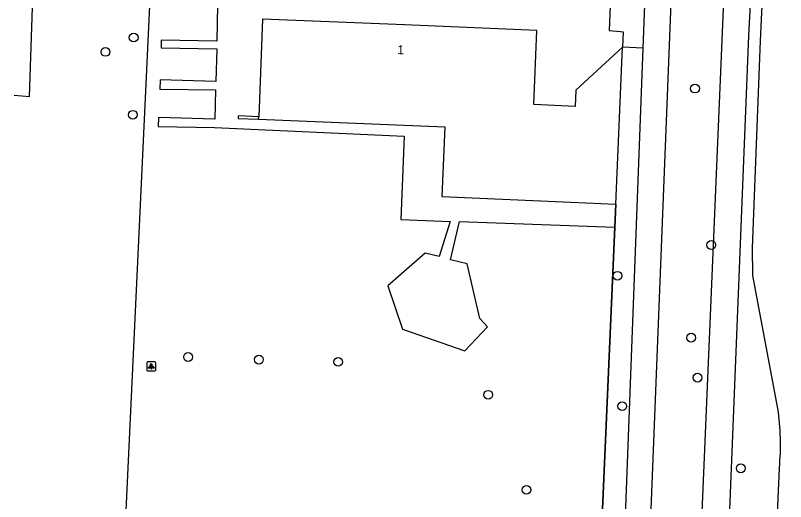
# Model space of a CAD drawing. Extents: x 159053 to 160041, y 380450 to 381422.
# Drawn here: x 159897.6 to 159983.4, y 380755.6 to 380809.7 of the extents above; entities that cross this region are included whole.
import ezdxf

# ---------------------------------------------------------------- set-up
doc = ezdxf.new("R2010")
doc.units = 0
for name, color, linetype in [('IMGEO_Boom', 7, 'Continuous'), ('IMGEO_Fietspad_gesloten', 7, 'Continuous'), ('IMGEO_Groenvoorziening', 7, 'Continuous'), ('IMGEO_Hek', 7, 'Continuous'), ('IMGEO_Lichtpunt', 7, 'Continuous'), ('IMGEO_Loofbos', 7, 'Continuous'), ('IMGEO_Muur', 7, 'Continuous'), ('IMGEO_Pand', 7, 'Continuous'), ('IMGEO_Pand_nummerreeks', 7, 'Continuous'), ('IMGEO_Waterloop', 7, 'Continuous')]:
    doc.layers.add(name, color=color, linetype=linetype)

msp = doc.modelspace()

# ---------------------------------------------------------------- linework, layer by layer
at = {"layer": 'IMGEO_Boom'}
for centre in [(159910.798, 380807.243), (159907.647, 380805.635), (159973.338, 380801.555), (159910.708, 380798.641), (159975.152, 380784.135), (159964.712, 380780.714), (159972.919, 380773.818), (159916.855, 380771.663), (159924.752, 380771.37), (159933.575, 380771.131), (159973.617, 380769.369), (159950.302, 380767.46), (159965.235, 380766.195), (159978.44, 380759.268), (159954.567, 380756.88)]:
    msp.add_circle(centre, 0.489, dxfattribs=at)
at = {"layer": 'IMGEO_Fietspad_gesloten'}
for points in [[(159979.746, 380815.858), (159979.289, 380807.437), (159976.994, 380750), (159976.032, 380725.916)], [(159976.649, 380814.868), (159973.899, 380750), (159973.294, 380735.725)]]:
    msp.add_lwpolyline(points, dxfattribs=at)
at = {"layer": 'IMGEO_Groenvoorziening'}
for points in [[(159922.465, 380837.691), (159945.016, 380836.716), (159945.689, 380836.687), (159945.523, 380830.904), (159944.744, 380830.927), (159944.231, 380819.979), (159964.236, 380819.097), (159963.771, 380808.022), (159965.045, 380807.904), (159965.344, 380807.876), (159965.27, 380806.182)], [(159920.181, 380812.937), (159920.078, 380806.836), (159913.857, 380806.952), (159913.841, 380806.103), (159920.058, 380805.987), (159919.954, 380802.343), (159913.737, 380802.521), (159913.725, 380801.487), (159919.927, 380801.418), (159919.834, 380798.164), (159913.554, 380798.344), (159913.538, 380797.336), (159919.808, 380797.235), (159940.92, 380796.248), (159940.581, 380786.96), (159946.044, 380786.772), (159944.85, 380782.87), (159943.273, 380783.216), (159939.124, 380779.591), (159940.75, 380774.772), (159947.706, 380772.359), (159950.226, 380775.04), (159949.378, 380775.935), (159947.959, 380782.05), (159946.108, 380782.473), (159947.088, 380786.736), (159964.402, 380786.14)]]:
    msp.add_lwpolyline(points, dxfattribs=at)
at = {"layer": 'IMGEO_Hek'}
for points in [[(159962.235, 380736.106), (159909.17, 380737.936), (159912.66, 380812.394)], [(159962.235, 380736.106), (159964.512, 380788.686)]]:
    msp.add_lwpolyline(points, dxfattribs=at)
at = {"layer": 'IMGEO_Lichtpunt'}
for p, q in [((159912.254, 380771.019), (159912.254, 380770.212)), ((159912.254, 380771.019), (159912.254, 380770.212)), ((159913.156, 380771.114), (159912.348, 380771.114)), ((159913.156, 380771.114), (159912.348, 380771.114)), ((159913.25, 380770.212), (159913.25, 380771.019)), ((159913.25, 380770.212), (159913.25, 380771.019)), ((159912.348, 380770.118), (159913.156, 380770.118)), ((159912.348, 380770.118), (159913.156, 380770.118))]:
    msp.add_line(p, q, dxfattribs=at)
for points in [[(159912.628, 380770.683), (159912.667, 380770.655), (159912.479, 380770.393), (159912.441, 380770.42), (159912.628, 380770.683)], [(159912.73, 380770.635), (159912.777, 380770.635), (159912.777, 380770.313), (159912.73, 380770.313), (159912.73, 380770.635)], [(159912.84, 380770.655), (159912.878, 380770.682), (159913.065, 380770.42), (159913.026, 380770.392), (159912.84, 380770.655)]]:
    msp.add_lwpolyline(points, dxfattribs=at)
msp.add_circle((159912.753, 380770.817), 0.0994, dxfattribs=at)
for centre, start, end in [((159912.348, 380771.019), 90, 180), ((159912.348, 380771.019), 90, 180), ((159913.156, 380771.019), 0, 90), ((159913.156, 380771.019), 0, 90), ((159912.348, 380770.212), 180, 270), ((159912.348, 380770.212), 180, 270), ((159913.156, 380770.212), 270, 0), ((159913.156, 380770.212), 270, 360)]:
    msp.add_arc(centre, 0.0946, start, end, dxfattribs=at)
at = {"layer": 'IMGEO_Loofbos'}
for points in [[(159897.461, 380800.812), (159899.181, 380800.678), (159899.599, 380812.861)], [(159962.235, 380736.106), (159909.17, 380737.936), (159912.66, 380812.394)], [(159967.567, 380806.065), (159965.27, 380806.182)], [(159964.512, 380788.686), (159964.402, 380786.14)], [(159964.402, 380786.14), (159962.235, 380736.106)]]:
    msp.add_lwpolyline(points, dxfattribs=at)
at = {"layer": 'IMGEO_Muur'}
msp.add_lwpolyline([(159924.724, 380798.403), (159922.44, 380798.514), (159922.429, 380798.23), (159924.713, 380798.138)], dxfattribs=at)
at = {"layer": 'IMGEO_Pand'}
for points in [[(159965.27, 380806.182), (159960.074, 380801.377), (159960, 380799.578), (159955.394, 380799.768), (159955.734, 380808.041), (159940.955, 380808.648), (159925.159, 380809.298), (159924.724, 380798.403)], [(159964.512, 380788.686), (159965.27, 380806.182)], [(159924.713, 380798.138), (159924.724, 380798.403)], [(159924.713, 380798.138), (159945.467, 380797.307), (159945.13, 380789.524), (159959.517, 380788.902), (159964.512, 380788.686)]]:
    msp.add_lwpolyline(points, dxfattribs=at)
at = {"layer": 'IMGEO_Waterloop'}
for points in [[(159982.569, 380765.948), (159979.781, 380780.733), (159979.738, 380783.825), (159980.639, 380806.855), (159981.885, 380833.671), (159983.436, 380833.578), (159983.436, 380833.578)], [(159967.567, 380806.065), (159968.111, 380820.525)], [(159970.919, 380817.724), (159968.237, 380750), (159967.977, 380743.428)], [(159965.209, 380743.382), (159965.458, 380750), (159967.567, 380806.065)], [(159981.67, 380722.402), (159981.491, 380726.633), (159981.537, 380731.582), (159982.336, 380750), (159982.739, 380759.305)]]:
    msp.add_lwpolyline(points, dxfattribs=at)
msp.add_arc((159956.11, 380761.947), 26.76, 354.33349, 8.59837, dxfattribs=at)

# ---------------------------------------------------------------- texts
at = {"layer": 'IMGEO_Pand_nummerreeks'}
msp.add_text('1', height=1, rotation=357.64514, dxfattribs=at).set_placement((159940.15, 380805.399))

doc.saveas('drawing.dxf')
